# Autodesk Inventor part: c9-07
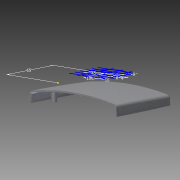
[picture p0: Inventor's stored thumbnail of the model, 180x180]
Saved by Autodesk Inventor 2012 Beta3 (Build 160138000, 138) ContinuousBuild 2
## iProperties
Created: 2010-12
Part Number: c9-07
Material: Default
Document SubType Name: Modeling
Designer: Beta-8540w
Density: 1 g/cm^3
Author: Beta-8540w
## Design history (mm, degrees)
sketch "Sketch1"
  geometry: L1 (-60, -12)-(60, -12); L2 (60, -12)-(60, 12); L3 (60, 12)-(-60, 12); L4 (-60, 12)-(-60, -12); A1 r 350 centre (0, -332.819) between (60, 12) and (-60, 12); A2 r 350 centre (0, 332.819) between (-60, -12) and (60, -12); 3 further points
  constraints: 8 end point, 4 point on circle, 2 centre point, 2 midpoint, 2 parallel, 1 equal radius, 1 horizontal, 1 horizontal alignment, 1 perpendicular, 1 vertical alignment
  dimensions: "d0" = 120 distance of L3.end L2.end; "d1" = 24 distance of L2.end L1.end; "d2" = 350 radius of A1
workplane "Work Plane4"
sketch "Sketch5"
  geometry: L1 (-60, 12)-(-60, -12) reference; L2 (60, -12)-(60, 12) reference; L3 (-58, 10.314)-(-58, -10.314); L4 (58, -10.314)-(58, 10.314); A1 r 350 centre (0, 332.819) between (-60, -12) and (60, -12) reference; A2 r 350 centre (0, -332.819) between (60, 12) and (-60, 12) reference; A3 r 348 centre (0, 332.819) between (-58, -10.314) and (58, -10.314); A4 r 348 centre (0, -332.819) between (58, 10.314) and (-58, 10.314); 1 further point
  constraints: 4 end point, 4 point on circle, 2 centre point, 3 other
  dimensions: "d37" = 2 distance between parallel lines of L2 L4
sketch "Sketch6"
  geometry: L1 (-60, 0)-(60, 0); L2 (60, 0)-(58.843, 22.085); L3 (-60, 0)-(-58.779, 23.307); A1 r 691.758 centre (630.81, -36.204) between (-60, 0) and (-58, -100); A2 r 691.758 centre (-630.81, -36.204) between (58, -100) and (60, 0); 1 further point
  constraints: 6 end point, 4 point on circle, 2 centre point, 2 tangent, 1 horizontal
  dimensions: "d53" = 87 deg angle of L1 L3; "d54" = 87 deg angle of L1 L2 (= d53)
sketch "Sketch7"
  geometry: L1 (17.181, 0)-(12, 0) reference; L2 (15.181, -100)-(10.314, -100) reference; L3 (17.181, 0)-(16.768, 11.838); A1 r 911.322 centre (-893.585, -31.805) between (15.181, -100) and (17.181, 0); 1 further point
  constraints: 2 end point, 2 point on circle, 1 centre point, 1 tangent
  dimensions: "d56" = 88 deg angle of L1 L3
feature "LoftSrf2" sketch "Sketch5", "Sketch6", "Sketch7" dims "d57" = 0, "d58" = 90 deg, "d59" = 0, "d60" = 90 deg, "d61" = 0, "d62" = 90 deg, "d63" = 0, "d64" = 90 deg, "d65" = 0, "d66" = 90 deg
sketch "Sketch2"
  geometry: L1 (-75, -16)-(75, -16); L2 (-75, -60)-(75, -60); A1 r 183.781 centre (0, -183.781) between (75, -16) and (-75, -16); 2 further points
  constraints: 4 end point, 3 point on circle, 1 centre point, 1 coincident, 1 horizontal, 1 parallel
  dimensions: "d5" = 16 distance from line of point (0, 0) L1; "d7" = 60 distance from line of point (0, 0) L2; "d55" = 150 distance of L1.start L1.end
feature "RevolutionSrf1" sketch "Sketch2" dims angle "d8" = 40 deg
patch "Boundary Patch1" dims "d13" = 0, "d67" = 0, "d68" = 0, "d69" = 0, "d70" = 0
workplane "Work Plane1"
sketch "Sketch3"
  geometry: L1 (52, -85)-(52, -73); L2 (38, -73)-(38, -85); A1 r 7 centre (45, -73) between (52, -73) and (38, -73); A2 r 7 centre (45, -85) between (38, -85) and (52, -85); 1 further point
  constraints: 4 end point, 4 point on circle, 4 tangent, 2 centre point, 1 parallel, 1 vertical
  dimensions: "d15" = 12 distance of L1.start L1.end; "d16" = 7 radius of A1; "d50" = 45 horizontal distance of A1.centre point (0, 0); "d51" = 85 vertical distance of point (0, 0) A2.centre
extrude_surface "ExtrusionSrf2" sketch "Sketch3" dims "d19" = 14, "d20" = 5 deg
pattern_linear "Rectangular Pattern1" dims "d23" = 90
workplane "Work Plane2"
feature "Sculpt1"
sketch "Sketch4"
  geometry: L1 (-24.5, 6)-(24.5, 6); L2 (27.5, 3)-(27.5, -3); L3 (24.5, -6)-(-24.5, -6); L4 (-27.5, -3)-(-27.5, 3); A1 r 3 centre (-24.5, 3) between (-24.5, 6) and (-27.5, 3); A2 r 3 centre (24.5, 3) between (27.5, 3) and (24.5, 6); A3 r 3 centre (24.5, -3) between (24.5, -6) and (27.5, -3); A4 r 3 centre (-24.5, -3) between (-27.5, -3) and (-24.5, -6); 6 further points
  constraints: 8 end point, 8 point on circle, 8 tangent, 6 point on line, 4 centre point, 3 equal radius, 2 midpoint, 2 parallel, 1 horizontal, 1 horizontal alignment, 1 perpendicular, 1 vertical alignment
  dimensions: "d28" = 55 distance of point (27.5, -6) point (-27.5, -6); "d29" = 12 distance of point (27.5, 6) point (27.5, -6); "d30" = 3 radius of A1
extrude_surface "ExtrusionSrf6" sketch "Sketch4" dims "d31" = 14, "d32" = 45 deg
patch "Boundary Patch2" dims "d33" = 0, "d34" = 0
fillet "Fillet1" dims "d79" = 4, "d80" = 3, "d81" = 1
feature "Sculpt2"
node "Splitting Plane 1"
shell "Shell1" dims "d83" = 2
split "Split1"
  body "Solid1"
feature "Lip1" dims "d171" = 1, "d172" = 1, "d173" = 0, "d174" = 0, "d175" = 0, "d176" = 0
feature "Lip2" dims "d177" = 1, "d178" = 1, "d179" = 0, "d180" = 0, "d181" = 0, "d182" = 0.5
split "Split3"
  node "Back"
sketch "Sketch9"
  geometry: L1 (50.167, -73)-(50.167, -85) reference; L2 (39.833, -85)-(39.833, -73) reference; L3 (45, -73)-(45, -85); L4 (45, -85)-(39.833, -85); A1 r 5.167 centre (45, -73) between (50.167, -73) and (39.833, -73) reference; A2 r 5.167 centre (45, -85) between (39.833, -85) and (50.167, -85) reference; 5 further points
  constraints: 4 end point, 1 horizontal, 1 midpoint, 1 parallel, 1 perpendicular, 1 vertical, 3 other
  dimensions: "d86" = 90 distance of point (45, -79) point (-45, -79); "d89" = 40 distance of point (45, -79) point (45, -39)
  node "Projected Loop1"
feature "Boss1" dims "d92" = 0, "d93" = 0, "d94" = 7, "d95" = 2, "d96" = 0.5, "d97" = 6, "d98" = 1.25, "d99" = 3.5, "d100" = 2.5 deg, "d101" = 2.5 deg, "d102" = 2.5 deg, "d103" = 2.5 deg, "d104" = 90 deg, "d107" = 2, "d108" = 2, "d109" = 10, "d110" = 0, "d111" = 10 deg, "d112" = 2.5 deg, "d113" = 0, "d114" = 0, "d115" = 0, "d116" = 360 deg
feature "Boss2" dims "d117" = 3, "d118" = 0, "d119" = 6, "d120" = 3, "d121" = 9.5, "d122" = 2 deg, "d123" = 1 deg, "d126" = 2, "d127" = 2, "d128" = 10, "d129" = 0, "d130" = 10 deg, "d131" = 2.5 deg, "d132" = 0, "d133" = 0, "d134" = 0, "d135" = 360 deg
workplane "Work Plane6"
sketch "Sketch10"
  geometry: L1 (24, -85)-(-24, -85); L2 (-30, -79)-(-30, -51); L3 (-24, -45)-(24, -45); L4 (30, -51)-(30, -79); L5 (54.344, -100)-(-54.344, -100) reference; A1 r 6 centre (-24, -51) between (-24, -45) and (-30, -51); A2 r 6 centre (24, -51) between (30, -51) and (24, -45); A3 r 6 centre (24, -79) between (24, -85) and (30, -79); A4 r 6 centre (-24, -79) between (-30, -79) and (-24, -85); 5 further points
  constraints: 8 end point, 8 point on circle, 8 tangent, 6 point on line, 4 centre point, 3 equal radius, 2 parallel, 1 horizontal, 1 midpoint, 1 perpendicular, 1 vertical alignment
  dimensions: "d137" = 60 distance of point (-30, -45) point (30, -45); "d138" = 40 distance of point (-30, -85) point (-30, -45); "d139" = 15 distance between parallel lines of L5 L1; "d141" = 6 radius of A2
feature "Rest1" sketch "Sketch10" dims "d142" = 5, "d143" = 0, "d144" = 0, "d145" = 0, "d146" = 2 deg, "d147" = 2 deg, "d148" = 2
feature "Rule Fillet1" dims "d149" = 2, "d150" = 1
workplane "Work Plane7"
sketch "Sketch11" dims "d154" = 16, "d155" = 8, "d161" = 10, "d168" = 10
  geometry: L1 (-13, -39.858)-(-13, -90.142); L2 (-25.187, -85)-(29.449, -85); L3 (0, -39.858)-(0, -90.142); L4 (13, -39.858)-(13, -90.142); L5 (-25.187, -77)-(29.449, -77); L6 (-25.187, -69)-(29.449, -69); L7 (-25.187, -61)-(29.449, -61); L8 (-25.187, -53)-(29.449, -53); L9 (-25.187, -45)-(29.449, -45); C1 r 22.5 at (0, -65); 3 further points; 1 other entity
  constraints: 18 end point, 2 coincident, 2 vertical, 1 centre point, 1 horizontal, 1 midpoint, 1 perpendicular, 1 vertical alignment, 23 other
  dimensions: "d152" = 45 diameter of C1; "d153" = 65 distance of point (0, 0) C1.centre; "d158" = 13 distance of L1.start L3.start; "d165" = 8 distance of L2.start L5.start; "d170" = 4 distance from line of L7 point (0, -65)
body "Srf2"
body "Srf3"
body "Srf4"
body "Srf5"
body "Srf6"
body "Srf7"
body "Srf8"
body "Srf9"
body "Srf11"
feature "Stitch Surface1"
body "Srf12"
extrude_surface "ExtrusionSrf3"
extrude_surface "ExtrusionSrf4"
extrude_surface "ExtrusionSrf5"
node "Front"
node "Back - Top"
node "Back - Bottom"
other parameters: "d14" = -24, "d52" = -6
